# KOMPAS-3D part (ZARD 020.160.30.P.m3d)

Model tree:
1. Плоскость XY
2. Плоскость ZX
3. Плоскость ZY
4. Ось X
5. Ось Y
6. Ось Z
7. Начало координат
8. Смещенная плоскость:3
     Расстояние = 97
9. Смещенная плоскость:4
     Расстояние = 97
10. Булева операция:1
11. Булева операция:2
12. Булева операция:3
13. Булева операция:4
14. Булева операция:7
15. Булева операция:8
